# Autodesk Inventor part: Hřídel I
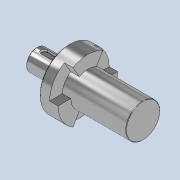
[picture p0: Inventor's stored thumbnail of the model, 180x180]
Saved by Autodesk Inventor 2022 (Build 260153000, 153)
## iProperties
Created: 2025-05
Part Number: Hřídel I
Material: Všeobecné
Document SubType Name: Modeling
Designer: jbart
Density: 1 g/cm^3
Appearance: Broušená
Mass: 617.229 g
Surface Area: 636.147 cm^2
Volume: 617.229 cm^3
Author: jbart
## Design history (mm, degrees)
sketch "Náčrt1"
  geometry: L1 (0, 0)-(100, 0); L2 (0, 0)-(0, 25); L3 (0, 25)-(76, 25); L4 (76, 25)-(76, 70); L5 (76, 70)-(100, 70); L6 (100, 70)-(100, 0)
  constraints: 12 end point, 4 perpendicular, 1 horizontal, 1 vertical
  dimensions: "d0" = 100 distance of L1.start L1.end; "d2" = 76 distance of L2.end L3.end; "d3" = 50 diameter of L3 L1; "d4" = 140 diameter of L5 L1
revolve "Rotace1" sketch "Náčrt1" stored, may be unused: angle "d5" = 90 deg
node "Pracovní rovina1"
sketch "Náčrt2"
  geometry: L1 (-10, 0)-(-60, 0); L2 (-18, 8)-(-52, 8); L3 (-52, -8)-(-18, -8); L4 (-76, 70)-(-76, -70) reference; A1 r 8 centre (-18, 0) between (-18, -8) and (-18, 8); A2 r 8 centre (-52, 0) between (-52, 8) and (-52, -8); 2 further points
  constraints: 8 end point, 6 point on circle, 4 tangent, 2 centre point, 2 point on line, 1 horizontal, 1 horizontal alignment, 1 midpoint, 1 parallel
  dimensions: "d7" = 50 distance of L1.start L1.end; "d8" = 16 diameter of A2; "d16" = 16 distance from line of L4 L1.end
extrude "Vysunutí1" cut sketch "Náčrt2" distance "d10" = 6.2; taper "d11" = 0 deg
fillet "Zaoblení1" dims "d12" = 0.6
chamfer "Zkosení1" distance "d13" = 1; stored, may be unused: second distance "d14" = 2, angle "d15" = 45 deg
sketch "Náčrt3"
  geometry: L1 (0, 0)-(0, 70); L2 (-20, 34.641)-(-35, 60.622); L3 (20, 34.641)-(35, 60.622); L4 (-20, 34.641)-(0, 0); L5 (20, 34.641)-(0, 0); A1 r 70 centre (0, 0) between (0, 70) and (-35, 60.622) reference; A2 r 40 centre (0, 0) between (20, 34.641) and (-20, 34.641); 1 further point
  constraints: 10 end point, 5 point on circle, 2 coincident, 1 centre point, 1 vertical
  dimensions: "d17" = 80 diameter of A2; "d18" = 60 deg angle of L2 L3; "d19" = 30 deg angle of L2 L1; "d20" = 30 deg angle of L1 L4; "d21" = 60 deg angle of L4 L5
extrude "Vysunutí2" join sketch "Náčrt3" distance "d22" = 20; taper "d23" = 0 deg
pattern_circular "Kruhové pole1" dims angle "d25" = 360 deg
chamfer "Zkosení2" distance "d27" = 2; stored, may be unused: second distance "d28" = 2, angle "d29" = 45 deg
fillet "Zaoblení2" dims "d30" = 2
sketch "Náčrt5"
  geometry: C1 r 40 at (0, 0); 1 further point
  constraints: 1 centre point, 1 coincident
  dimensions: "d32" = 80 diameter of C1
extrude "Vysunutí3" join sketch "Náčrt5" distance "d33" = 150; taper "d34" = 0 deg
chamfer "Zkosení3" distance "d35" = 1; stored, may be unused: second distance "d36" = 2, angle "d37" = 45 deg
node "Těleso1"
other parameters: "d6" = 25
